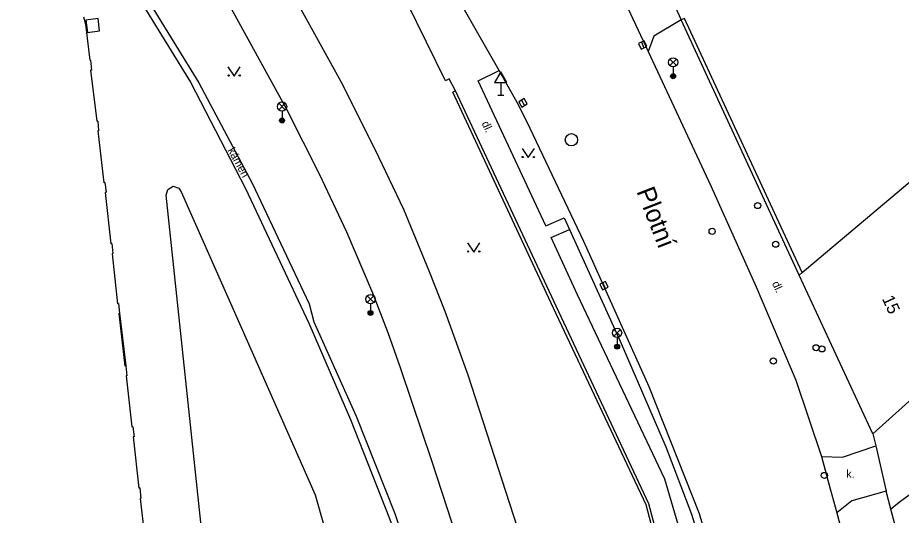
# Model space of a CAD drawing. Extents: x -598341 to -594502, y -1162301 to -1161406.
# Drawn here: x -597650 to -597578.3, y -1161713.5 to -1161673.1 of the extents above; entities that cross this region are included whole.
import ezdxf

# ---------------------------------------------------------------- set-up
doc = ezdxf.new("R2010")
doc.units = 0
for name, color, linetype in [('Vrstva 10', 7, 'Continuous'), ('Vrstva 11', 7, 'Continuous'), ('Vrstva 26', 7, 'Continuous'), ('Vrstva 27', 7, 'Continuous'), ('Vrstva 28', 7, 'Continuous'), ('Vrstva 33', 7, 'Continuous'), ('Vrstva 34', 7, 'Continuous'), ('Vrstva 36', 7, 'Continuous'), ('Vrstva 40', 7, 'Continuous'), ('Vrstva 46', 7, 'Continuous'), ('Vrstva 49', 7, 'Continuous'), ('Vrstva 5', 7, 'Continuous'), ('Vrstva 7', 7, 'Continuous'), ('Vrstva 8', 7, 'Continuous')]:
    doc.layers.add(name, color=color, linetype=linetype)

msp = doc.modelspace()

# ---------------------------------------------------------------- linework, layer by layer
at = {"layer": 'Vrstva 10'}
for p, q in [((-597601.33, -1161670.46), (-597598.81, -1161675.86)), ((-597598.81, -1161675.86), (-597593.72, -1161686.79)), ((-597593.72, -1161686.79), (-597590.03, -1161694.97)), ((-597590.03, -1161694.97), (-597586.82, -1161702.57)), ((-597586.82, -1161702.57), (-597584.72, -1161708.75)), ((-597584.72, -1161708.75), (-597584.02, -1161711.38)), ((-597584.02, -1161711.38), (-597583.5, -1161713.34)), ((-597583.5, -1161713.34), (-597582.97, -1161715.3))]:
    msp.add_line(p, q, dxfattribs=at)
for points in [[(-597610.91, -1161677.42), (-597615.12, -1161669.99), (-597619.69, -1161661.76), (-597621.87, -1161657.96), (-597626.47, -1161650), (-597632.47, -1161638.84), (-597635.09, -1161634.33), (-597636.33, -1161632.57), (-597638.15, -1161630.21), (-597639.32, -1161628.73), (-597643.16, -1161624.07), (-597646.55, -1161619.99), (-597646.95, -1161619.53)], [(-597608.39, -1161682.12), (-597609.17, -1161680.53), (-597609.44, -1161680.02), (-597610.91, -1161677.42)], [(-597592.75, -1161719.93), (-597594.64, -1161713.42), (-597598.73, -1161703.1), (-597604.02, -1161691.29), (-597608.39, -1161682.12)]]:
    msp.add_lwpolyline(points, dxfattribs=at)
at = {"layer": 'Vrstva 11'}
for p, q in [((-597606.68, -1161690.98), (-597605.2, -1161690.33)), ((-597605.2, -1161690.33), (-597601.08, -1161699.38)), ((-597604.53, -1161695.63), (-597606.68, -1161690.98)), ((-597597.46, -1161710.61), (-597604.53, -1161695.63)), ((-597641.72, -1161697.13), (-597641.22, -1161701.4)), ((-597601.08, -1161699.38), (-597597.38, -1161707.97)), ((-597597.38, -1161707.97), (-597595.3, -1161713.45)), ((-597594.54, -1161720.41), (-597597.46, -1161710.61)), ((-597595.3, -1161713.45), (-597593.6, -1161718.74))]:
    msp.add_line(p, q, dxfattribs=at)
for points in [[(-597649.14, -1161631.8), (-597646.69, -1161636.3), (-597643.84, -1161641.53), (-597635.57, -1161656.71), (-597627.73, -1161671.08), (-597623.76, -1161678.3), (-597620.99, -1161683.81), (-597618.67, -1161688.68), (-597616.58, -1161693.73), (-597615.31, -1161696.97)], [(-597654.47, -1161632.39), (-597651.15, -1161638.49), (-597648.27, -1161643.75), (-597640.06, -1161658.85), (-597632.05, -1161673.52), (-597628.2, -1161680.5), (-597625.5, -1161685.85), (-597623.3, -1161690.52), (-597621.19, -1161695.46), (-597619.95, -1161698.68)], [(-597614.44, -1161679.07), (-597614.95, -1161678.09), (-597615.25, -1161678.26), (-597630.69, -1161646.82)], [(-597641.47, -1161669.42), (-597640.9, -1161669.3), (-597635.29, -1161678.41), (-597630.95, -1161686.55), (-597627.71, -1161693.43), (-597626.33, -1161696.35)], [(-597641.47, -1161669.42), (-597635.96, -1161678.36), (-597631.49, -1161686.99), (-597626.36, -1161697.93)], [(-597596.12, -1161673.31), (-597598.34, -1161674.63), (-597598.81, -1161675.86)], [(-597607.12, -1161690.04), (-597612.61, -1161678.26), (-597610.91, -1161677.42)], [(-597631.88, -1161698.19), (-597625.84, -1161711.88), (-597622.41, -1161723.97), (-597632.21, -1161726.63), (-597634.99, -1161715.4), (-597637.94, -1161687.54), (-597637.8, -1161687.07), (-597637.38, -1161686.8), (-597636.91, -1161686.97), (-597636.73, -1161687.27), (-597631.88, -1161698.19)], [(-597607.12, -1161690.04), (-597605.63, -1161689.37), (-597605.2, -1161690.33)], [(-597626.33, -1161696.35), (-597625.94, -1161697.81), (-597622.51, -1161705.47), (-597619.38, -1161713.38), (-597616.78, -1161721.13), (-597614.46, -1161728.64), (-597612.21, -1161737.03)], [(-597615.31, -1161696.97), (-597613.45, -1161702.12), (-597607.31, -1161721.1), (-597599.59, -1161745.93)], [(-597626.36, -1161697.93), (-597622.96, -1161705.76), (-597619.82, -1161713.78), (-597617.17, -1161721.29), (-597614.82, -1161728.91), (-597612.66, -1161737.06)], [(-597619.95, -1161698.68), (-597618.94, -1161701.52), (-597617.98, -1161704.35), (-597616.41, -1161709.08), (-597608.16, -1161734.3), (-597604.14, -1161747.18)], [(-597561.06, -1161699.58), (-597564.92, -1161702.34), (-597566.91, -1161704.1), (-597578.33, -1161712.41), (-597579.1, -1161713.03)], [(-597584.72, -1161708.75), (-597583.04, -1161708.82), (-597580.32, -1161707.9)], [(-597579.49, -1161711.58), (-597582.28, -1161712.37), (-597583.5, -1161713.34)]]:
    msp.add_lwpolyline(points, dxfattribs=at)
at = {"layer": 'Vrstva 26'}
msp.add_lwpolyline([(-597644.332, -1161674.32), (-597643.34, -1161674.192), (-597643.468, -1161673.2), (-597644.46, -1161673.328)], close=True, dxfattribs=at)
at = {"layer": 'Vrstva 27'}
for p, q in [((-597599.353, -1161675.122), (-597599.147, -1161675.578)), ((-597609.085, -1161679.823), (-597608.835, -1161680.257)), ((-597602.491, -1161694.661), (-597602.289, -1161695.119))]:
    msp.add_line(p, q, dxfattribs=at)
for points in [[(-597599.581, -1161675.226), (-597599.374, -1161675.681), (-597598.919, -1161675.474), (-597599.126, -1161675.019)], [(-597609.301, -1161679.948), (-597609.052, -1161680.381), (-597608.619, -1161680.132), (-597608.868, -1161679.699)], [(-597602.72, -1161694.762), (-597602.518, -1161695.22), (-597602.06, -1161695.018), (-597602.262, -1161694.56)]]:
    msp.add_lwpolyline(points, close=True, dxfattribs=at)
msp.add_circle((-597605.04, -1161683.04), 0.5, dxfattribs=at)
at = {"layer": 'Vrstva 28'}
for centre in [(-597589.92, -1161688.38), (-597593.61, -1161690.48), (-597588.45, -1161691.52), (-597585.17, -1161699.93), (-597584.7, -1161700.02), (-597588.64, -1161701), (-597584.5, -1161710.3)]:
    msp.add_circle(centre, 0.25, dxfattribs=at)
at = {"layer": 'Vrstva 33'}
for p, q in [((-597597.045, -1161677.02), (-597596.515, -1161676.49)), ((-597597.045, -1161676.49), (-597596.515, -1161677.02)), ((-597596.78, -1161677.13), (-597596.78, -1161677.88)), ((-597628.795, -1161680.61), (-597628.265, -1161680.08)), ((-597628.795, -1161680.08), (-597628.265, -1161680.61)), ((-597628.53, -1161680.72), (-597628.53, -1161681.47)), ((-597621.615, -1161696.25), (-597621.085, -1161695.72)), ((-597621.615, -1161695.72), (-597621.085, -1161696.25)), ((-597621.35, -1161696.36), (-597621.35, -1161697.11)), ((-597601.595, -1161698.98), (-597601.065, -1161698.45)), ((-597601.595, -1161698.45), (-597601.065, -1161698.98)), ((-597601.33, -1161699.09), (-597601.33, -1161699.84))]:
    msp.add_line(p, q, dxfattribs=at)
for centre, radius in [((-597596.78, -1161676.755), 0.375), ((-597596.78, -1161677.88), 0.2), ((-597596.78, -1161677.88), 0.145), ((-597596.78, -1161677.88), 0.0876), ((-597628.53, -1161680.345), 0.375), ((-597628.53, -1161681.47), 0.2), ((-597628.53, -1161681.47), 0.145), ((-597628.53, -1161681.47), 0.0876), ((-597621.35, -1161695.985), 0.375), ((-597621.35, -1161697.11), 0.2), ((-597621.35, -1161697.11), 0.145), ((-597621.35, -1161697.11), 0.0876), ((-597601.33, -1161698.715), 0.375), ((-597601.33, -1161699.84), 0.2), ((-597601.33, -1161699.84), 0.145), ((-597601.33, -1161699.84), 0.0876)]:
    msp.add_circle(centre, radius, dxfattribs=at)
at = {"layer": 'Vrstva 34'}
for p, q in [((-597610.77, -1161678.402), (-597610.77, -1161679.42)), ((-597611.02, -1161679.42), (-597610.52, -1161679.42))]:
    msp.add_line(p, q, dxfattribs=at)
msp.add_lwpolyline([(-597611.27, -1161678.402), (-597610.27, -1161678.402), (-597610.77, -1161677.536)], close=True, dxfattribs=at)
at = {"layer": 'Vrstva 36'}
for points in [[(-597632.92, -1161677.12), (-597632.42, -1161677.87), (-597631.92, -1161677.12)], [(-597609.04, -1161683.74), (-597608.54, -1161684.49), (-597608.04, -1161683.74)], [(-597613.47, -1161691.41), (-597612.97, -1161692.16), (-597612.47, -1161691.41)]]:
    msp.add_lwpolyline(points, dxfattribs=at)
for centre in [(-597632.87, -1161677.82), (-597631.971, -1161677.82), (-597608.99, -1161684.44), (-597608.091, -1161684.44), (-597613.42, -1161692.11), (-597612.52, -1161692.11)]:
    msp.add_circle(centre, 0.05, dxfattribs=at)
at = {"layer": 'Vrstva 5'}
for p, q in [((-597644.64, -1161673.07), (-597644.49, -1161673.65)), ((-597644.49, -1161673.65), (-597644.35, -1161674.79)), ((-597644.35, -1161674.79), (-597644.15, -1161676.58)), ((-597644.08, -1161676.57), (-597644.15, -1161676.58)), ((-597644.08, -1161676.57), (-597644, -1161677.39)), ((-597644, -1161677.39), (-597644.07, -1161677.4)), ((-597644.07, -1161677.4), (-597643.56, -1161681.53)), ((-597643.49, -1161681.52), (-597643.56, -1161681.53)), ((-597643.49, -1161681.52), (-597643.42, -1161682.31)), ((-597643.42, -1161682.31), (-597643.49, -1161682.32)), ((-597643.49, -1161682.32), (-597643, -1161686.53)), ((-597586.3, -1161693.83), (-597576.69, -1161685.72)), ((-597642.93, -1161686.52), (-597643, -1161686.53)), ((-597642.93, -1161686.52), (-597642.82, -1161687.3)), ((-597642.82, -1161687.3), (-597642.89, -1161687.31)), ((-597642.89, -1161687.31), (-597642.42, -1161691.48)), ((-597642.35, -1161691.47), (-597642.42, -1161691.48)), ((-597642.35, -1161691.47), (-597642.26, -1161692.28)), ((-597642.26, -1161692.28), (-597642.33, -1161692.29)), ((-597642.33, -1161692.29), (-597641.88, -1161696.35)), ((-597586.54, -1161694.03), (-597586.3, -1161693.83)), ((-597580.57, -1161706.91), (-597586.54, -1161694.03)), ((-597641.81, -1161696.34), (-597641.88, -1161696.35)), ((-597641.81, -1161696.34), (-597641.72, -1161697.13)), ((-597641.72, -1161697.13), (-597641.79, -1161697.14)), ((-597641.79, -1161697.14), (-597641.29, -1161701.41)), ((-597571.78, -1161699.01), (-597580.57, -1161706.91)), ((-597641.22, -1161701.4), (-597641.29, -1161701.41)), ((-597641.22, -1161701.4), (-597641.12, -1161702.2)), ((-597641.12, -1161702.2), (-597641.19, -1161702.21)), ((-597641.19, -1161702.21), (-597640.72, -1161706.36)), ((-597640.65, -1161706.35), (-597640.72, -1161706.36)), ((-597640.65, -1161706.35), (-597640.55, -1161707.15)), ((-597640.55, -1161707.15), (-597640.62, -1161707.16)), ((-597640.62, -1161707.16), (-597640.15, -1161711.32)), ((-597640.08, -1161711.31), (-597640.15, -1161711.32)), ((-597640.08, -1161711.31), (-597639.99, -1161712.16)), ((-597639.99, -1161712.16), (-597640.06, -1161712.17)), ((-597640.06, -1161712.17), (-597639.55, -1161716.38))]:
    msp.add_line(p, q, dxfattribs=at)
at = {"layer": 'Vrstva 7'}
msp.add_line((-597586.54, -1161694.03), (-597596.12, -1161673.31), dxfattribs=at)
for points in [[(-597586.3, -1161693.83), (-597595.85, -1161673.18), (-597596.12, -1161673.31)], [(-597614.44, -1161679.07), (-597614.67, -1161679.18)], [(-597596.78, -1161721.02), (-597598.98, -1161712.69), (-597606.48, -1161696.71), (-597614.67, -1161679.18)], [(-597596.54, -1161720.96), (-597598.74, -1161712.6), (-597606.25, -1161696.6), (-597614.44, -1161679.07)], [(-597580.57, -1161706.91), (-597580.32, -1161707.9)], [(-597579.1, -1161713.03), (-597579.49, -1161711.58)], [(-597577.37, -1161719.52), (-597579.1, -1161713.03)]]:
    msp.add_lwpolyline(points, dxfattribs=at)
at = {"layer": 'Vrstva 8'}
for p, q in [((-597597.75, -1161669.82), (-597596.12, -1161673.31)), ((-597580.32, -1161707.9), (-597579.49, -1161711.58))]:
    msp.add_line(p, q, dxfattribs=at)

# ---------------------------------------------------------------- texts
at = {"layer": 'Vrstva 40'}
for s, rotation, p in [('dl.', 295.04205, (-597612.34, -1161681.7)), ('kámen', 298.70996, (-597632.97, -1161683.89)), ('dl.', 295.04205, (-597588.77, -1161694.7))]:
    msp.add_text(s, height=0.65, rotation=rotation, dxfattribs=at).set_placement(p)
msp.add_text('k.', height=0.65, dxfattribs=at).set_placement((-597582.72, -1161710.49))
at = {"layer": 'Vrstva 46'}
msp.add_text('15', height=1, rotation=294.89, dxfattribs=at).set_placement((-597579.84, -1161695.94))
at = {"layer": 'Vrstva 49'}
msp.add_text('Plotní', height=1.5, rotation=291.26271, dxfattribs=at).set_placement((-597599.77, -1161687.22))

doc.saveas('drawing.dxf')
